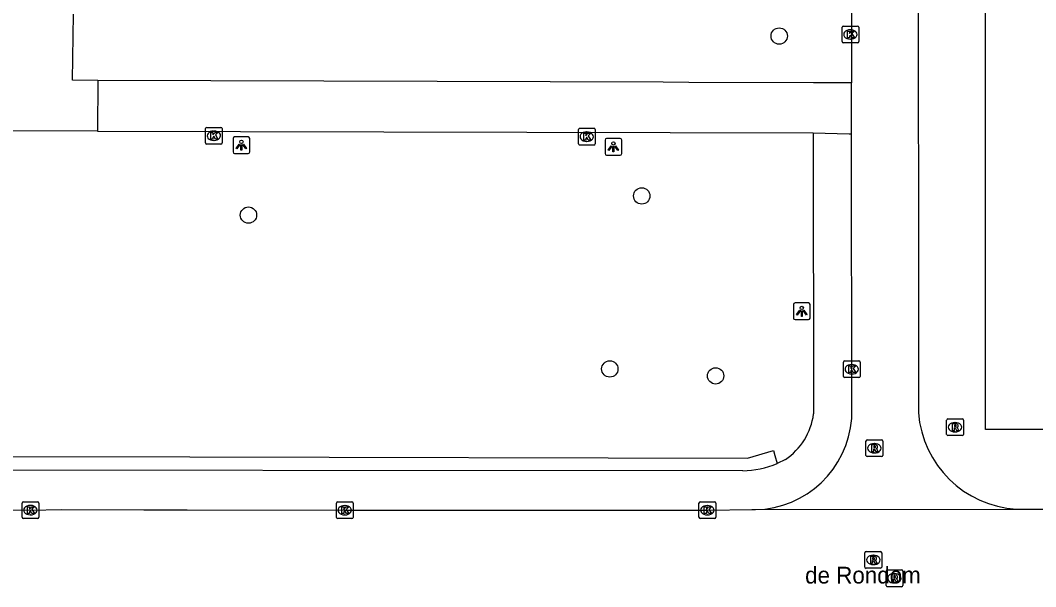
# Model space of a CAD drawing. Extents: x 161477 to 163040, y 383680 to 384868.
# Drawn here: x 162291.9 to 162352.6, y 384173.8 to 384207.7 of the extents above; entities that cross this region are included whole.
import ezdxf

# ---------------------------------------------------------------- set-up
doc = ezdxf.new("R2010")
doc.units = 0
for name, color, linetype in [('IMGEO_Boom', 7, 'Continuous'), ('IMGEO_Groenvoorziening', 7, 'Continuous'), ('IMGEO_Kolk', 7, 'Continuous'), ('IMGEO_Lichtpunt', 7, 'Continuous'), ('IMGEO_Openbare_ruimte_label', 7, 'Continuous'), ('IMGEO_Pand', 7, 'Continuous'), ('IMGEO_Rijbaan_lokaal_open', 7, 'Continuous'), ('IMGEO_Rioolput', 7, 'Continuous'), ('IMGEO_Voetpad_open', 7, 'Continuous')]:
    doc.layers.add(name, color=color, linetype=linetype)

msp = doc.modelspace()

# ---------------------------------------------------------------- linework, layer by layer
at = {"layer": 'IMGEO_Boom'}
for centre in [(162337.249, 384206.72), (162329.032, 384197.162), (162305.516, 384196.013), (162327.122, 384186.819), (162333.446, 384186.403)]:
    msp.add_circle(centre, 0.489, dxfattribs=at)
at = {"layer": 'IMGEO_Groenvoorziening'}
msp.add_lwpolyline([(162252.934, 384181.584), (162254.223, 384181.583), (162302.009, 384181.564), (162335.355, 384181.49), (162336.907, 384181.934), (162336.989, 384181.646), (162337.128, 384181.162)], dxfattribs=at)
at = {"layer": 'IMGEO_Kolk'}
for p, q in [((162341.006, 384206.389), (162341.006, 384207.241)), ((162341.081, 384207.315), (162341.933, 384207.315)), ((162341.494, 384207.095), (162341.519, 384207.095)), ((162342.007, 384207.241), (162342.007, 384206.389)), ((162341.517, 384206.535), (162341.492, 384206.535)), ((162341.933, 384206.315), (162341.081, 384206.315)), ((162302.944, 384200.333), (162302.944, 384201.185)), ((162303.019, 384201.259), (162303.871, 384201.259)), ((162303.432, 384201.039), (162303.457, 384201.039)), ((162303.945, 384201.185), (162303.945, 384200.333)), ((162325.24, 384200.277), (162325.24, 384201.129)), ((162325.315, 384201.203), (162326.167, 384201.203)), ((162326.241, 384201.129), (162326.241, 384200.277)), ((162303.455, 384200.479), (162303.43, 384200.479)), ((162325.751, 384200.423), (162325.726, 384200.423)), ((162325.728, 384200.983), (162325.753, 384200.983)), ((162303.871, 384200.259), (162303.019, 384200.259)), ((162326.167, 384200.203), (162325.315, 384200.203)), ((162341.087, 384186.372), (162341.087, 384187.224)), ((162341.162, 384187.298), (162342.014, 384187.298)), ((162341.575, 384187.078), (162341.6, 384187.078)), ((162342.088, 384187.224), (162342.088, 384186.372)), ((162341.598, 384186.518), (162341.573, 384186.518)), ((162342.014, 384186.298), (162341.162, 384186.298)), ((162291.978, 384177.95), (162291.978, 384178.802)), ((162292.053, 384178.876), (162292.905, 384178.876)), ((162292.466, 384178.656), (162292.491, 384178.656)), ((162292.979, 384178.802), (162292.979, 384177.95)), ((162310.775, 384177.944), (162310.775, 384178.796)), ((162310.85, 384178.87), (162311.702, 384178.87)), ((162311.263, 384178.65), (162311.288, 384178.65)), ((162311.776, 384178.796), (162311.776, 384177.944)), ((162332.452, 384177.947), (162332.452, 384178.799)), ((162332.527, 384178.873), (162333.379, 384178.873)), ((162332.94, 384178.653), (162332.965, 384178.653)), ((162333.453, 384178.799), (162333.453, 384177.947)), ((162292.489, 384178.096), (162292.464, 384178.096)), ((162311.286, 384178.09), (162311.261, 384178.09)), ((162332.963, 384178.093), (162332.938, 384178.093)), ((162292.905, 384177.876), (162292.053, 384177.876)), ((162311.702, 384177.87), (162310.85, 384177.87)), ((162333.379, 384177.873), (162332.527, 384177.873))]:
    msp.add_line(p, q, dxfattribs=at)
for points in [[(162341.006, 384206.389), (162341.006, 384207.241)], [(162341.081, 384207.315), (162341.933, 384207.315)], [(162342.007, 384207.241), (162342.007, 384206.389)], [(162341.327, 384207.015), (162341.45, 384207.015), (162341.45, 384206.864), (162341.58, 384207.015), (162341.744, 384207.015), (162341.598, 384206.864), (162341.751, 384206.615), (162341.599, 384206.615), (162341.514, 384206.779), (162341.45, 384206.712), (162341.45, 384206.615), (162341.327, 384206.615), (162341.327, 384207.015)], [(162341.933, 384206.315), (162341.081, 384206.315)], [(162302.944, 384200.333), (162302.944, 384201.185)], [(162303.019, 384201.259), (162303.871, 384201.259)], [(162303.945, 384201.185), (162303.945, 384200.333)], [(162325.24, 384200.277), (162325.24, 384201.129)], [(162325.315, 384201.203), (162326.167, 384201.203)], [(162326.241, 384201.129), (162326.241, 384200.277)], [(162303.265, 384200.959), (162303.388, 384200.959), (162303.388, 384200.808), (162303.518, 384200.959), (162303.682, 384200.959), (162303.536, 384200.808), (162303.689, 384200.559), (162303.537, 384200.559), (162303.452, 384200.723), (162303.388, 384200.656), (162303.388, 384200.559), (162303.265, 384200.559), (162303.265, 384200.959)], [(162325.561, 384200.903), (162325.684, 384200.903), (162325.684, 384200.752), (162325.814, 384200.903), (162325.978, 384200.903), (162325.832, 384200.752), (162325.985, 384200.503), (162325.833, 384200.503), (162325.748, 384200.667), (162325.684, 384200.6), (162325.684, 384200.503), (162325.561, 384200.503), (162325.561, 384200.903)], [(162303.871, 384200.259), (162303.019, 384200.259)], [(162326.167, 384200.203), (162325.315, 384200.203)], [(162341.087, 384186.372), (162341.087, 384187.224)], [(162341.162, 384187.298), (162342.014, 384187.298)], [(162342.088, 384187.224), (162342.088, 384186.372)], [(162341.408, 384186.998), (162341.531, 384186.998), (162341.531, 384186.847), (162341.661, 384186.998), (162341.825, 384186.998), (162341.679, 384186.847), (162341.832, 384186.598), (162341.68, 384186.598), (162341.595, 384186.762), (162341.531, 384186.695), (162341.531, 384186.598), (162341.408, 384186.598), (162341.408, 384186.998)], [(162342.014, 384186.298), (162341.162, 384186.298)], [(162291.978, 384177.95), (162291.978, 384178.802)], [(162292.053, 384178.876), (162292.905, 384178.876)], [(162292.299, 384178.576), (162292.422, 384178.576), (162292.422, 384178.425), (162292.552, 384178.576), (162292.716, 384178.576), (162292.57, 384178.425), (162292.723, 384178.176), (162292.571, 384178.176), (162292.486, 384178.34), (162292.422, 384178.273), (162292.422, 384178.176), (162292.299, 384178.176), (162292.299, 384178.576)], [(162292.979, 384178.802), (162292.979, 384177.95)], [(162310.775, 384177.944), (162310.775, 384178.796)], [(162310.85, 384178.87), (162311.702, 384178.87)], [(162311.096, 384178.57), (162311.219, 384178.57), (162311.219, 384178.419), (162311.349, 384178.57), (162311.513, 384178.57), (162311.367, 384178.419), (162311.52, 384178.17), (162311.368, 384178.17), (162311.283, 384178.334), (162311.219, 384178.267), (162311.219, 384178.17), (162311.096, 384178.17), (162311.096, 384178.57)], [(162311.776, 384178.796), (162311.776, 384177.944)], [(162332.452, 384177.947), (162332.452, 384178.799)], [(162332.527, 384178.873), (162333.379, 384178.873)], [(162332.773, 384178.573), (162332.896, 384178.573), (162332.896, 384178.422), (162333.026, 384178.573), (162333.19, 384178.573), (162333.044, 384178.422), (162333.197, 384178.173), (162333.045, 384178.173), (162332.96, 384178.337), (162332.896, 384178.27), (162332.896, 384178.173), (162332.773, 384178.173), (162332.773, 384178.573)], [(162333.453, 384178.799), (162333.453, 384177.947)], [(162292.905, 384177.876), (162292.053, 384177.876)], [(162311.702, 384177.87), (162310.85, 384177.87)], [(162333.379, 384177.873), (162332.527, 384177.873)]]:
    msp.add_lwpolyline(points, dxfattribs=at)
for centre, start, end in [((162341.083, 384207.239), 91.55205, 178.44795), ((162341.083, 384207.239), 91.55205, 178.44795), ((162341.931, 384207.239), 1.55205, 88.44795), ((162341.931, 384207.239), 1.55205, 88.44795), ((162341.083, 384206.391), 181.55205, 268.44795), ((162341.083, 384206.391), 181.55205, 268.44795), ((162341.931, 384206.391), 271.55205, 358.44795), ((162341.931, 384206.391), 271.55205, 358.44795), ((162303.021, 384201.183), 91.55205, 178.44795), ((162303.021, 384201.183), 91.55205, 178.44795), ((162303.869, 384201.183), 1.55205, 88.44795), ((162303.869, 384201.183), 1.55205, 88.44795), ((162325.317, 384201.127), 91.55205, 178.44795), ((162325.317, 384201.127), 91.55205, 178.44795), ((162326.165, 384201.127), 1.55205, 88.44795), ((162326.165, 384201.127), 1.55205, 88.44795), ((162303.021, 384200.335), 181.55205, 268.44795), ((162303.021, 384200.335), 181.55205, 268.44795), ((162303.869, 384200.335), 271.55205, 358.44795), ((162303.869, 384200.335), 271.55205, 358.44795), ((162325.317, 384200.279), 181.55205, 268.44795), ((162325.317, 384200.279), 181.55205, 268.44795), ((162326.165, 384200.279), 271.55205, 358.44795), ((162326.165, 384200.279), 271.55205, 358.44795), ((162341.164, 384187.222), 91.55205, 178.44795), ((162341.164, 384187.222), 91.55205, 178.44795), ((162342.012, 384187.222), 1.55205, 88.44795), ((162342.012, 384187.222), 1.55205, 88.44795), ((162341.164, 384186.374), 181.55205, 268.44795), ((162341.164, 384186.374), 181.55205, 268.44795), ((162342.012, 384186.374), 271.55205, 358.44795), ((162342.012, 384186.374), 271.55205, 358.44795), ((162292.055, 384178.8), 91.55205, 178.44795), ((162292.055, 384178.8), 91.55205, 178.44795), ((162292.903, 384178.8), 1.55205, 88.44795), ((162292.903, 384178.8), 1.55205, 88.44795), ((162310.852, 384178.794), 91.55205, 178.44795), ((162310.852, 384178.794), 91.55205, 178.44795), ((162311.7, 384178.794), 1.55205, 88.44795), ((162311.7, 384178.794), 1.55205, 88.44795), ((162332.529, 384178.797), 91.55205, 178.44795), ((162332.529, 384178.797), 91.55205, 178.44795), ((162333.377, 384178.797), 1.55205, 88.44795), ((162333.377, 384178.797), 1.55205, 88.44795), ((162292.055, 384177.952), 181.55205, 268.44795), ((162292.055, 384177.952), 181.55205, 268.44795), ((162292.903, 384177.952), 271.55205, 358.44795), ((162292.903, 384177.952), 271.55205, 358.44795), ((162310.852, 384177.946), 181.55205, 268.44795), ((162310.852, 384177.946), 181.55205, 268.44795), ((162311.7, 384177.946), 271.55205, 358.44795), ((162311.7, 384177.946), 271.55205, 358.44795), ((162332.529, 384177.949), 181.55205, 268.44795), ((162332.529, 384177.949), 181.55205, 268.44795), ((162333.377, 384177.949), 271.55205, 358.44795), ((162333.377, 384177.949), 271.55205, 358.44795)]:
    msp.add_arc(centre, 0.0765, start, end, dxfattribs=at)
for centre, major_axis, ratio, start_param, end_param in [((162341.493, 384206.815), (-0.387, 0.002), 0.722429, 4.712389, 7.853982), ((162341.518, 384206.815), (-0.39, 0.002), 0.717154, 1.570796, 4.712389), ((162303.431, 384200.759), (-0.387, 0.002), 0.722429, 4.712389, 7.853982), ((162303.456, 384200.759), (-0.39, 0.002), 0.717154, 1.570796, 4.712389), ((162325.727, 384200.703), (-0.387, 0.002), 0.722429, 4.712389, 7.853982), ((162325.752, 384200.703), (-0.39, 0.002), 0.717154, 1.570796, 4.712389), ((162341.574, 384186.798), (-0.387, 0.002), 0.722429, 4.712389, 7.853982), ((162341.599, 384186.798), (-0.39, 0.002), 0.717154, 1.570796, 4.712389), ((162292.465, 384178.376), (-0.387, 0.002), 0.722429, 4.712389, 7.853982), ((162292.49, 384178.376), (-0.39, 0.002), 0.717154, 1.570796, 4.712389), ((162311.262, 384178.37), (-0.387, 0.002), 0.722429, 4.712389, 7.853982), ((162311.287, 384178.37), (-0.39, 0.002), 0.717154, 1.570796, 4.712389), ((162332.939, 384178.373), (-0.387, 0.002), 0.722429, 4.712389, 7.853982), ((162332.964, 384178.373), (-0.39, 0.002), 0.717154, 1.570796, 4.712389)]:
    msp.add_ellipse(centre, major_axis=major_axis, ratio=ratio, start_param=start_param, end_param=end_param, dxfattribs=at)
at = {"layer": 'IMGEO_Lichtpunt'}
for p, q in [((162304.592, 384200.596), (162304.592, 384199.789)), ((162304.592, 384200.596), (162304.592, 384199.789)), ((162305.494, 384200.691), (162304.686, 384200.691)), ((162305.494, 384200.691), (162304.686, 384200.691)), ((162305.588, 384199.789), (162305.588, 384200.596)), ((162305.588, 384199.789), (162305.588, 384200.596)), ((162326.835, 384200.498), (162326.835, 384199.691)), ((162326.835, 384200.498), (162326.835, 384199.691)), ((162327.737, 384200.593), (162326.929, 384200.593)), ((162327.737, 384200.593), (162326.929, 384200.593)), ((162327.831, 384199.691), (162327.831, 384200.498)), ((162327.831, 384199.691), (162327.831, 384200.498)), ((162304.686, 384199.695), (162305.494, 384199.695)), ((162304.686, 384199.695), (162305.494, 384199.695)), ((162326.929, 384199.597), (162327.737, 384199.597)), ((162326.929, 384199.597), (162327.737, 384199.597)), ((162339.003, 384190.761), (162338.195, 384190.761)), ((162339.003, 384190.761), (162338.195, 384190.761)), ((162338.101, 384190.666), (162338.101, 384189.859)), ((162338.101, 384190.666), (162338.101, 384189.859)), ((162339.097, 384189.859), (162339.097, 384190.666)), ((162339.097, 384189.859), (162339.097, 384190.666)), ((162338.195, 384189.765), (162339.003, 384189.765)), ((162338.195, 384189.765), (162339.003, 384189.765))]:
    msp.add_line(p, q, dxfattribs=at)
for points in [[(162304.966, 384200.26), (162305.005, 384200.232), (162304.817, 384199.97), (162304.779, 384199.997), (162304.966, 384200.26)], [(162305.068, 384200.212), (162305.115, 384200.212), (162305.115, 384199.89), (162305.068, 384199.89), (162305.068, 384200.212)], [(162305.178, 384200.232), (162305.216, 384200.259), (162305.403, 384199.997), (162305.364, 384199.969), (162305.178, 384200.232)], [(162327.209, 384200.162), (162327.248, 384200.134), (162327.06, 384199.872), (162327.022, 384199.899), (162327.209, 384200.162)], [(162327.311, 384200.114), (162327.358, 384200.114), (162327.358, 384199.792), (162327.311, 384199.792), (162327.311, 384200.114)], [(162327.421, 384200.134), (162327.459, 384200.161), (162327.646, 384199.899), (162327.607, 384199.871), (162327.421, 384200.134)], [(162338.475, 384190.33), (162338.514, 384190.302), (162338.326, 384190.04), (162338.288, 384190.067), (162338.475, 384190.33)], [(162338.577, 384190.282), (162338.624, 384190.282), (162338.624, 384189.96), (162338.577, 384189.96), (162338.577, 384190.282)], [(162338.687, 384190.302), (162338.725, 384190.329), (162338.912, 384190.067), (162338.873, 384190.039), (162338.687, 384190.302)]]:
    msp.add_lwpolyline(points, dxfattribs=at)
for centre in [(162305.091, 384200.394), (162327.334, 384200.296), (162338.6, 384190.464)]:
    msp.add_circle(centre, 0.0994, dxfattribs=at)
for centre, start, end in [((162304.686, 384200.596), 90, 180), ((162304.686, 384200.596), 90, 180), ((162305.494, 384200.596), 0, 90), ((162305.494, 384200.596), 0, 90), ((162326.929, 384200.498), 90, 180), ((162326.929, 384200.498), 90, 180), ((162327.737, 384200.498), 0, 90), ((162327.737, 384200.498), 0, 90), ((162304.686, 384199.789), 180, 270), ((162304.686, 384199.789), 180, 270), ((162305.494, 384199.789), 270, 0), ((162305.494, 384199.789), 270, 360), ((162326.929, 384199.691), 180, 270), ((162326.929, 384199.691), 180, 270), ((162327.737, 384199.691), 270, 0), ((162327.737, 384199.691), 270, 360), ((162338.195, 384190.666), 90, 180), ((162338.195, 384190.666), 90, 180), ((162339.003, 384190.666), 0, 90), ((162339.003, 384190.666), 0, 90), ((162338.195, 384189.859), 180, 270), ((162338.195, 384189.859), 180, 270), ((162339.003, 384189.859), 270, 0), ((162339.003, 384189.859), 270, 360)]:
    msp.add_arc(centre, 0.0946, start, end, dxfattribs=at)
at = {"layer": 'IMGEO_Pand'}
msp.add_lwpolyline([(162382.059, 384183.395), (162373.395, 384183.376), (162373.395, 384183.196), (162349.59, 384183.191), (162349.595, 384212.314), (162349.598, 384218.339)], dxfattribs=at)
at = {"layer": 'IMGEO_Rijbaan_lokaal_open'}
for points in [[(162341.539, 384241.386), (162341.555, 384222.16), (162341.557, 384219.804), (162341.571, 384203.926)], [(162345.569, 384216.327), (162345.575, 384184.19)], [(162341.574, 384200.876), (162341.571, 384203.926)], [(162341.588, 384183.859), (162341.574, 384200.876)], [(162252.922, 384178.516), (162259.203, 384178.493), (162261.436, 384178.45), (162273.795, 384178.392), (162275.26, 384178.393), (162281.276, 384178.418), (162292.479, 384178.377), (162294.329, 384178.415), (162299.266, 384178.402), (162301.859, 384178.396), (162311.276, 384178.371), (162332.953, 384178.374), (162335.618, 384178.406), (162335.829, 384178.406)], [(162335.829, 384178.406), (162351.438, 384178.435)], [(162351.438, 384178.435), (162354.103, 384178.434), (162370.356, 384178.487), (162373.047, 384178.488), (162382.179, 384178.509)]]:
    msp.add_lwpolyline(points, dxfattribs=at)
for centre, radius, start, end in [((162351.814, 384184.683), 6.259, 184.51353, 266.55167), ((162335.711, 384184.298), 5.893, 271.14387, 355.72946)]:
    msp.add_arc(centre, radius, start, end, dxfattribs=at)
at = {"layer": 'IMGEO_Rioolput'}
for p, q in [((162347.263, 384182.907), (162347.263, 384183.759)), ((162347.338, 384183.833), (162348.19, 384183.833)), ((162347.751, 384183.613), (162347.776, 384183.613)), ((162348.264, 384183.759), (162348.264, 384182.907)), ((162348.19, 384182.833), (162347.338, 384182.833)), ((162347.774, 384183.053), (162347.749, 384183.053)), ((162342.438, 384181.648), (162342.438, 384182.5)), ((162342.513, 384182.574), (162343.365, 384182.574)), ((162342.926, 384182.354), (162342.951, 384182.354)), ((162343.439, 384182.5), (162343.439, 384181.648)), ((162342.949, 384181.794), (162342.924, 384181.794)), ((162343.365, 384181.574), (162342.513, 384181.574)), ((162342.377, 384174.972), (162342.377, 384175.824)), ((162342.452, 384175.898), (162343.304, 384175.898)), ((162342.865, 384175.678), (162342.89, 384175.678)), ((162343.378, 384175.824), (162343.378, 384174.972)), ((162342.888, 384175.118), (162342.863, 384175.118)), ((162343.304, 384174.898), (162342.452, 384174.898)), ((162343.637, 384173.875), (162343.637, 384174.727)), ((162343.712, 384174.801), (162344.564, 384174.801)), ((162344.125, 384174.581), (162344.15, 384174.581)), ((162344.638, 384174.727), (162344.638, 384173.875)), ((162344.564, 384173.801), (162343.712, 384173.801)), ((162344.148, 384174.021), (162344.123, 384174.021))]:
    msp.add_line(p, q, dxfattribs=at)
for points in [[(162347.263, 384182.907), (162347.263, 384183.759)], [(162347.338, 384183.833), (162348.19, 384183.833)], [(162347.852, 384183.531), (162347.6, 384183.533), (162347.6, 384183.133)], [(162347.778, 384183.452), (162347.724, 384183.452), (162347.724, 384183.371)], [(162348.264, 384183.759), (162348.264, 384182.907)], [(162348.19, 384182.833), (162347.338, 384182.833)], [(162347.6, 384183.133), (162347.724, 384183.133), (162347.724, 384183.295), (162347.735, 384183.295)], [(162347.724, 384183.371), (162347.776, 384183.371)], [(162347.782, 384183.266), (162347.853, 384183.133), (162347.993, 384183.133), (162347.928, 384183.259)], [(162342.438, 384181.648), (162342.438, 384182.5)], [(162342.513, 384182.574), (162343.365, 384182.574)], [(162343.027, 384182.272), (162342.775, 384182.274), (162342.775, 384181.874)], [(162342.953, 384182.193), (162342.899, 384182.193), (162342.899, 384182.112)], [(162343.439, 384182.5), (162343.439, 384181.648)], [(162342.775, 384181.874), (162342.899, 384181.874), (162342.899, 384182.036), (162342.91, 384182.036)], [(162342.899, 384182.112), (162342.951, 384182.112)], [(162342.957, 384182.007), (162343.028, 384181.874), (162343.168, 384181.874), (162343.103, 384182)], [(162343.365, 384181.574), (162342.513, 384181.574)], [(162342.377, 384174.972), (162342.377, 384175.824)], [(162342.452, 384175.898), (162343.304, 384175.898)], [(162342.966, 384175.596), (162342.714, 384175.598), (162342.714, 384175.198)], [(162342.892, 384175.517), (162342.838, 384175.517), (162342.838, 384175.436)], [(162343.378, 384175.824), (162343.378, 384174.972)], [(162342.714, 384175.198), (162342.838, 384175.198), (162342.838, 384175.36), (162342.849, 384175.36)], [(162342.838, 384175.436), (162342.89, 384175.436)], [(162342.896, 384175.331), (162342.967, 384175.198), (162343.107, 384175.198), (162343.042, 384175.324)], [(162343.304, 384174.898), (162342.452, 384174.898)], [(162343.637, 384173.875), (162343.637, 384174.727)], [(162343.712, 384174.801), (162344.564, 384174.801)], [(162344.226, 384174.499), (162343.974, 384174.501), (162343.974, 384174.101)], [(162344.152, 384174.42), (162344.098, 384174.42), (162344.098, 384174.339)], [(162344.098, 384174.339), (162344.15, 384174.339)], [(162344.638, 384174.727), (162344.638, 384173.875)], [(162344.564, 384173.801), (162343.712, 384173.801)], [(162343.974, 384174.101), (162344.098, 384174.101), (162344.098, 384174.263), (162344.109, 384174.263)], [(162344.156, 384174.234), (162344.227, 384174.101), (162344.367, 384174.101), (162344.302, 384174.227)]]:
    msp.add_lwpolyline(points, dxfattribs=at)
for centre, radius, start, end in [((162347.34, 384183.757), 0.0765, 91.55205, 178.44795), ((162347.34, 384183.757), 0.0765, 91.55205, 178.44795), ((162347.784, 384183.356), 0.0964, 77.00612, 93.18647), ((162347.798, 384183.413), 0.0378, 276.66336, 79.67722), ((162347.851, 384183.421), 0.109, 350.36119, 89.41601), ((162348.188, 384183.757), 0.0765, 1.55205, 88.44795), ((162348.188, 384183.757), 0.0765, 1.55205, 88.44795), ((162347.34, 384182.909), 0.0765, 181.55205, 268.44795), ((162347.34, 384182.909), 0.0765, 181.55205, 268.44795), ((162347.734, 384183.242), 0.0533, 26.02933, 88.69889), ((162347.76, 384183.56), 0.19, 274.7715, 282.96867), ((162347.849, 384183.421), 0.112, 277.58423, 350.98172), ((162347.833, 384183.206), 0.108, 29.51342, 73.79051), ((162348.188, 384182.909), 0.0765, 271.55205, 358.44795), ((162348.188, 384182.909), 0.0765, 271.55205, 358.44795), ((162342.515, 384182.498), 0.0765, 91.55205, 178.44795), ((162342.515, 384182.498), 0.0765, 91.55205, 178.44795), ((162342.959, 384182.097), 0.0964, 77.00612, 93.18647), ((162343.026, 384182.162), 0.109, 350.36119, 89.41601), ((162343.363, 384182.498), 0.0765, 1.55205, 88.44795), ((162343.363, 384182.498), 0.0765, 1.55205, 88.44795), ((162342.515, 384181.65), 0.0765, 181.55205, 268.44795), ((162342.515, 384181.65), 0.0765, 181.55205, 268.44795), ((162342.909, 384181.983), 0.0533, 26.02933, 88.69889), ((162342.935, 384182.301), 0.19, 274.7715, 282.96867), ((162342.973, 384182.154), 0.0378, 276.66336, 79.67722), ((162343.024, 384182.162), 0.112, 277.58423, 350.98172), ((162343.008, 384181.947), 0.108, 29.51342, 73.79051), ((162343.363, 384181.65), 0.0765, 271.55205, 358.44795), ((162343.363, 384181.65), 0.0765, 271.55205, 358.44795), ((162342.454, 384175.822), 0.0765, 91.55205, 178.44795), ((162342.454, 384175.822), 0.0765, 91.55205, 178.44795), ((162342.898, 384175.421), 0.0964, 77.00612, 93.18647), ((162342.912, 384175.478), 0.0378, 276.66336, 79.67722), ((162342.965, 384175.486), 0.109, 350.36119, 89.41601), ((162343.302, 384175.822), 0.0765, 1.55205, 88.44795), ((162343.302, 384175.822), 0.0765, 1.55205, 88.44795), ((162342.454, 384174.974), 0.0765, 181.55205, 268.44795), ((162342.454, 384174.974), 0.0765, 181.55205, 268.44795), ((162342.848, 384175.307), 0.0533, 26.02933, 88.69889), ((162342.874, 384175.625), 0.19, 274.7715, 282.96867), ((162342.963, 384175.486), 0.112, 277.58423, 350.98172), ((162342.947, 384175.271), 0.108, 29.51342, 73.79051), ((162343.302, 384174.974), 0.0765, 271.55205, 358.44795), ((162343.302, 384174.974), 0.0765, 271.55205, 358.44795), ((162343.714, 384174.725), 0.0765, 91.55205, 178.44795), ((162343.714, 384174.725), 0.0765, 91.55205, 178.44795), ((162344.134, 384174.528), 0.19, 274.7715, 282.96867), ((162344.158, 384174.324), 0.0964, 77.00612, 93.18647), ((162344.172, 384174.381), 0.0378, 276.66336, 79.67722), ((162344.225, 384174.389), 0.109, 350.36119, 89.41601), ((162344.223, 384174.389), 0.112, 277.58423, 350.98172), ((162344.562, 384174.725), 0.0765, 1.55205, 88.44795), ((162344.562, 384174.725), 0.0765, 1.55205, 88.44795), ((162343.714, 384173.877), 0.0765, 181.55205, 268.44795), ((162343.714, 384173.877), 0.0765, 181.55205, 268.44795), ((162344.108, 384174.21), 0.0533, 26.02933, 88.69889), ((162344.207, 384174.174), 0.108, 29.51342, 73.79051), ((162344.562, 384173.877), 0.0765, 271.55205, 358.44795), ((162344.562, 384173.877), 0.0765, 271.55205, 358.44795)]:
    msp.add_arc(centre, radius, start, end, dxfattribs=at)
for centre, major_axis, ratio, start_param, end_param in [((162347.75, 384183.333), (-0.387, 0.002), 0.722429, 4.712389, 7.853982), ((162347.775, 384183.333), (-0.39, 0.002), 0.717154, 1.570796, 4.712389), ((162342.925, 384182.074), (-0.387, 0.002), 0.722429, 4.712389, 7.853982), ((162342.95, 384182.074), (-0.39, 0.002), 0.717154, 1.570796, 4.712389), ((162342.864, 384175.398), (-0.387, 0.002), 0.722429, 4.712389, 7.853982), ((162342.889, 384175.398), (-0.39, 0.002), 0.717154, 1.570796, 4.712389), ((162344.124, 384174.301), (-0.387, 0.002), 0.722429, 4.712389, 7.853982), ((162344.149, 384174.301), (-0.39, 0.002), 0.717154, 1.570796, 4.712389)]:
    msp.add_ellipse(centre, major_axis=major_axis, ratio=ratio, start_param=start_param, end_param=end_param, dxfattribs=at)
at = {"layer": 'IMGEO_Voetpad_open'}
for points in [[(162296.518, 384204.07), (162294.994, 384204.083), (162295.049, 384208.018)], [(162296.518, 384204.07), (162296.492, 384201.026)], [(162341.571, 384203.926), (162341.399, 384203.925), (162339.293, 384203.916), (162331.838, 384203.948), (162330.31, 384203.953), (162296.518, 384204.07)], [(162296.492, 384201.026), (162259.001, 384201.076), (162258.97, 384188.03), (162252.922, 384187.999), (162252.934, 384181.584)], [(162296.492, 384201.026), (162339.283, 384200.927)], [(162339.283, 384200.927), (162341.426, 384200.879), (162341.574, 384200.876)], [(162339.283, 384200.927), (162339.304, 384184.129)], [(162337.618, 384181.396), (162337.128, 384181.162)], [(162335.072, 384180.734), (162277.64, 384180.77), (162252.935, 384180.787)]]:
    msp.add_lwpolyline(points, dxfattribs=at)
for centre, radius, start, end in [((162335.42, 384184.639), 3.918, 304.13461, 352.52414), ((162334.99, 384186.278), 5.545, 270.84265, 292.67612)]:
    msp.add_arc(centre, radius, start, end, dxfattribs=at)

# ---------------------------------------------------------------- texts
at = {"layer": 'IMGEO_Openbare_ruimte_label'}
msp.add_text('de Rondom', height=1, rotation=0.0573, dxfattribs=at).set_placement((162338.8, 384173.988))

doc.saveas('drawing.dxf')
